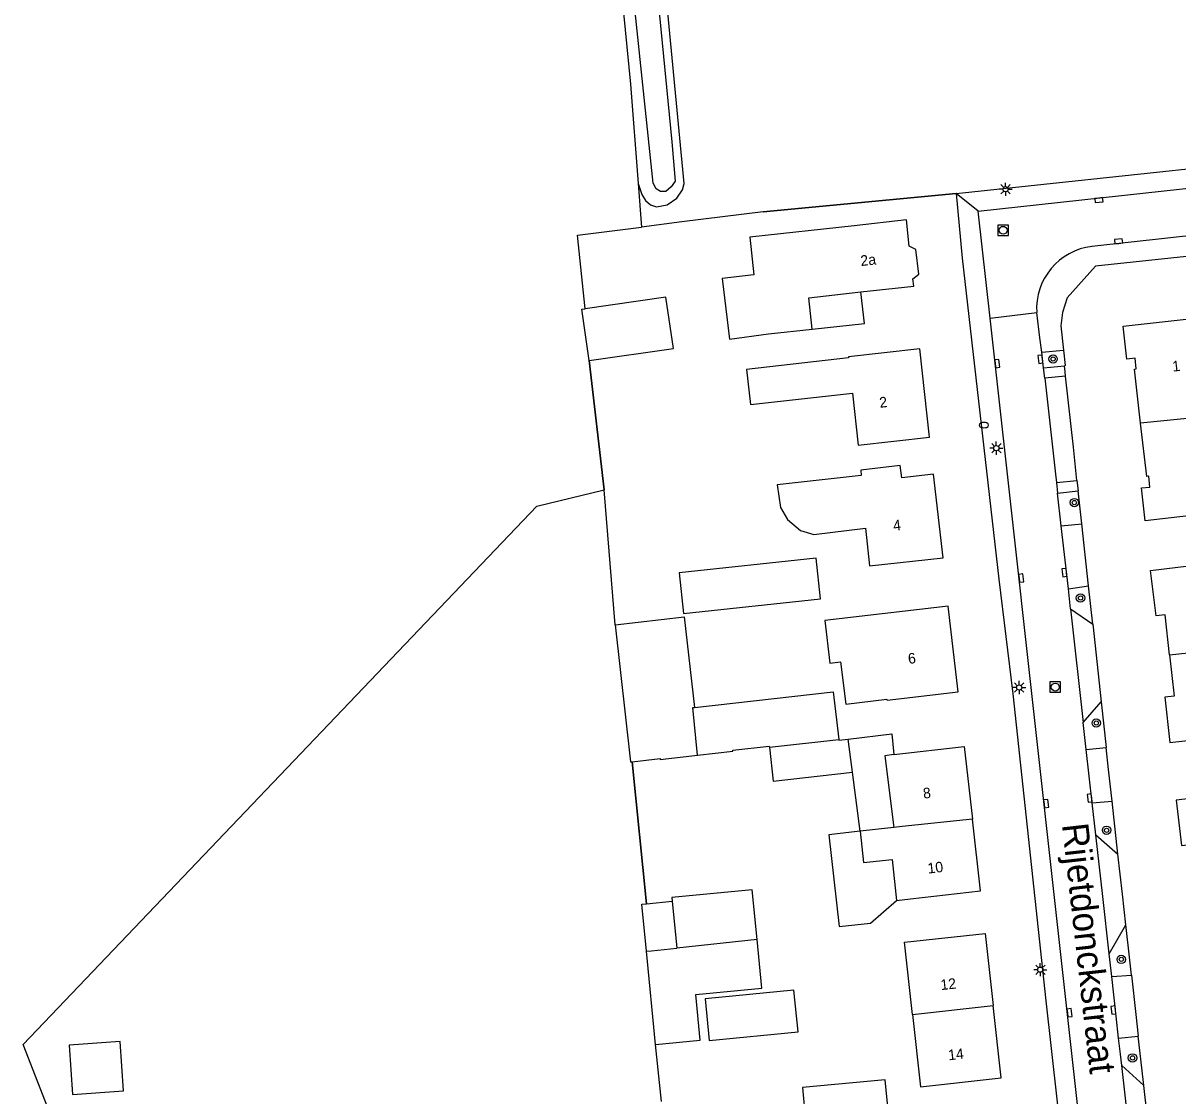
# Model space of a CAD drawing. Extents: x 140000 to 143000, y 403500 to 406000.
# Drawn here: x 140324.8 to 140434.8, y 403882.7 to 403984.8 of the extents above; entities that cross this region are included whole.
import ezdxf

# ---------------------------------------------------------------- set-up
doc = ezdxf.new("R2010")
doc.units = 0
for name, color, linetype in [('gg-afsc-erfafscheiding', 7, 'Continuous'), ('gg-afsc-hekwerk', 7, 'Continuous'), ('gg-anno-huisnummerreeks BGT', 7, 'Continuous'), ('gg-anno-openbare ruimte label', 7, 'Continuous'), ('gg-bbg-bijgebouw', 7, 'Continuous'), ('gg-bbg-gedigitaliseerde bijgebouw', 7, 'Continuous'), ('gg-bbg-hoofdgebouw', 7, 'Continuous'), ('gg-bbg-luifel en loopbrug', 7, 'Continuous'), ('gg-bbg-tussenscheiding', 7, 'Continuous'), ('gg-knt-verharding', 7, 'Continuous'), ('gg-knt-verharding nz', 7, 'Continuous'), ('gg-kntw-bovenkant insteek waterloop', 7, 'Continuous'), ('gg-kntw-waterlijn', 7, 'Continuous'), ('gt-grn-groengrens', 7, 'Continuous'), ('gt-grn-weggrens', 7, 'Continuous'), ('gt-symb-boom', 7, 'Continuous'), ('gt-symb-brandkraan', 7, 'Continuous'), ('gt-symb-kolk', 7, 'Continuous'), ('gt-symb-lichtmast', 7, 'Continuous'), ('gt-symb-rioolschacht', 7, 'Continuous')]:
    doc.layers.add(name, color=color, linetype=linetype)

# ---------------------------------------------------------------- blocks, each defined once
blk = doc.blocks.new('gt0-BOOM')
at = {"layer": 'gt-symb-boom'}
for radius in [0.4, 0.2]:
    blk.add_circle((0, 0), radius, dxfattribs=at)
blk = doc.blocks.new('gt0-KOLK')
at = {"layer": 'gt-symb-kolk'}
blk.add_lwpolyline([(0, 0), (0.38, 0), (0.38, 0.4), (-0.37, 0.4), (-0.37, 0), (0, 0)], dxfattribs=at)
blk = doc.blocks.new('gt0-LMAST')
at = {"layer": 'gt-symb-lichtmast'}
for p, q in [((-0.18, 0.17), (-0.45, 0.44)), ((-0.01, 0.25), (-0.01, 0.62)), ((0.17, 0.17), (0.44, 0.44)), ((-0.26, 0), (-0.63, 0)), ((-0.18, -0.18), (-0.45, -0.45)), ((-0.01, -0.25), (-0.01, -0.63)), ((0.44, -0.45), (0.17, -0.18)), ((0.24, 0), (0.62, 0))]:
    blk.add_line(p, q, dxfattribs=at)
blk.add_circle((-0.01, 0), 0.25, dxfattribs=at)
blk = doc.blocks.new('gt0-RS')
at = {"layer": 'gt-symb-rioolschacht'}
blk.add_lwpolyline([(-0.5, -0.5), (0.5, -0.5), (0.5, 0.5), (-0.5, 0.5)], close=True, dxfattribs=at)
blk.add_circle((0, 0), 0.375, dxfattribs=at)
blk = doc.blocks.new('gt0-BR')
at = {"layer": 'gt-symb-brandkraan'}
for centre, radius, start, end in [((-0.24, 0), 0.206, 107.5669, 252.4331), ((0.6, -2.66), 3, 106.892, 107.5669), ((0, -0.69), 0.938, 73.108, 106.892), ((-0.6, -2.66), 3, 72.4331, 73.108), ((0.24, 0), 0.206, 287.567, 72.4331), ((0.6, 2.66), 3, 252.4331, 253.108), ((0, 0.69), 0.938, 253.108, 286.8921), ((-0.6, 2.66), 3, 286.8921, 287.567)]:
    blk.add_arc(centre, radius, start, end, dxfattribs=at)

msp = doc.modelspace()

# ---------------------------------------------------------------- linework, layer by layer
at = {"layer": 'gg-afsc-erfafscheiding'}
for p, q in [((140423.89, 403953.71), (140424.05, 403952.23)), ((140381.2, 403927.56), (140380.15, 403940.39)), ((140385.61, 403882.17), (140385.05, 403887.6))]:
    msp.add_line(p, q, dxfattribs=at)
for points in [[(140378.37, 403957.63), (140377.61, 403964.65), (140383.71, 403965.42)], [(140439.21, 403962.85), (140439.2, 403962.98), (140426.93, 403961.68), (140424.25, 403958.67), (140423.81, 403957.27), (140423.66, 403956.01), (140423.89, 403953.71)]]:
    msp.add_lwpolyline(points, dxfattribs=at)
at = {"layer": 'gg-afsc-hekwerk'}
for p, q in [((140395.29, 403966.88), (140413.67, 403968.62)), ((140380.15, 403940.39), (140378.73, 403952.71)), ((140384.21, 403901.01), (140382.82, 403914.51)), ((140385.61, 403882.17), (140385.05, 403887.6))]:
    msp.add_line(p, q, dxfattribs=at)
at = {"layer": 'gg-bbg-bijgebouw'}
for p, q in [((140403.81, 403913.52), (140403.4, 403916.68)), ((140385.05, 403887.6), (140384.18, 403896.49))]:
    msp.add_line(p, q, dxfattribs=at)
for points in [[(140378.73, 403952.71), (140386.75, 403953.85), (140386.05, 403958.73), (140378.37, 403957.63)], [(140378.73, 403952.71), (140378.04, 403957.59), (140378.37, 403957.63)], [(140387.71, 403928.64), (140400.75, 403930.03), (140400.34, 403933.9), (140387.29, 403932.51), (140387.71, 403928.64)], [(140381.2, 403927.56), (140387.79, 403928.31), (140388.77, 403919.69)], [(140381.2, 403927.56), (140382.68, 403914.5), (140382.82, 403914.51)], [(140388.77, 403919.69), (140401.97, 403921.19), (140402.51, 403916.64)], [(140402.51, 403916.64), (140402.52, 403916.57), (140403.4, 403916.68)], [(140389.04, 403915.15), (140392.41, 403915.52), (140392.4, 403915.61), (140395.89, 403916.01), (140395.9, 403915.91)], [(140395.9, 403915.91), (140396.27, 403912.66), (140403.81, 403913.52)], [(140382.82, 403914.51), (140385.48, 403914.82), (140385.49, 403914.75), (140389.04, 403915.15)], [(140394.73, 403897.61), (140394.26, 403902.34), (140386.6, 403901.59)], [(140385.05, 403887.6), (140389.3, 403888.01), (140388.88, 403892.36), (140395.18, 403892.98), (140394.73, 403897.61)], [(140407.23, 403881.05), (140406.93, 403884.23), (140399.06, 403883.51), (140399.34, 403880.42)]]:
    msp.add_lwpolyline(points, dxfattribs=at)
at = {"layer": 'gg-bbg-gedigitaliseerde bijgebouw'}
for p in [(140384.21, 403901.01), (140386.6, 403901.59)]:
    msp.add_line(p, (140386.63, 403901.24), dxfattribs=at)
msp.add_lwpolyline([(140384.18, 403896.49), (140383.76, 403900.97), (140384.21, 403901.01)], dxfattribs=at)
at = {"layer": 'gg-bbg-hoofdgebouw'}
msp.add_line((140407.76, 403908.26), (140404.53, 403907.92), dxfattribs=at)
for points in [[(140409.21, 403963.59), (140408.94, 403966.1), (140403.97, 403965.54), (140394.03, 403964.46), (140394.43, 403960.88), (140391.4, 403960.53), (140392.11, 403954.73), (140395.8, 403955.24), (140399.97, 403955.7)], [(140409.56, 403960.49), (140410.12, 403960.93), (140409.85, 403963.28), (140409.21, 403963.59)], [(140431.24, 403946.74), (140430.65, 403951.89), (140430.83, 403951.91), (140430.73, 403952.93), (140429.94, 403952.83), (140429.57, 403955.97), (140439.86, 403957.14), (140439.27, 403962.43), (140442.69, 403962.82)], [(140404.61, 403959.24), (140409.64, 403959.79), (140409.56, 403960.49)], [(140399.97, 403955.7), (140399.64, 403958.69), (140404.61, 403959.24)], [(140393.71, 403951.87), (140394.09, 403948.52), (140403.8, 403949.61), (140404.36, 403944.66), (140411.15, 403945.42), (140410.21, 403953.81), (140403.43, 403953.06), (140403.44, 403952.96), (140393.71, 403951.87)], [(140438.18, 403947.43), (140438.76, 403942.37), (140440.59, 403942.58), (140441.05, 403938.54), (140431.68, 403937.46), (140431.32, 403940.58), (140432.11, 403940.67), (140432.01, 403941.7), (140431.82, 403941.68), (140431.24, 403946.74)], [(140412.44, 403933.94), (140411.53, 403941.89), (140408.49, 403941.54), (140408.35, 403942.71), (140404.59, 403942.29), (140404.64, 403941.76), (140396.65, 403940.88), (140396.95, 403938.72), (140397.63, 403937.58), (140398.85, 403936.52), (140400.12, 403936.16), (140405.04, 403936.74), (140405.43, 403933.16), (140412.44, 403933.94)], [(140434, 403924.69), (140433.57, 403928.52), (140432.71, 403928.42), (140432.17, 403932.72), (140437.13, 403933.34), (140440.13, 403933.68), (140441.06, 403925.48)], [(140407.09, 403920.48), (140407.1, 403920.38), (140413.88, 403921.17), (140412.93, 403929.34), (140401.17, 403927.97), (140401.66, 403923.91), (140402.68, 403924.03), (140403.16, 403920.01), (140407.09, 403920.48)], [(140434, 403924.69), (140434.43, 403920.77), (140433.56, 403920.68), (140434.02, 403916.37), (140441.99, 403917.23), (140441.06, 403925.48)], [(140407.76, 403915.21), (140414.43, 403915.96), (140415.22, 403909.07)], [(140407.76, 403915.21), (140406.88, 403915.09), (140407.76, 403908.26)], [(140443.5, 403903.66), (140442.59, 403911.8), (140434.64, 403910.87), (140435.14, 403906.56), (140436.01, 403906.66), (140436.43, 403902.87)], [(140408, 403901.3), (140409.32, 403901.46), (140416, 403902.22), (140415.22, 403909.07)], [(140404.53, 403907.92), (140404.87, 403904.92), (140407.58, 403905.22), (140408, 403901.3)], [(140409.51, 403890.46), (140408.76, 403897.34), (140416.45, 403898.18), (140417.2, 403891.31)], [(140409.51, 403890.46), (140410.27, 403883.58), (140417.96, 403884.43), (140417.2, 403891.31)]]:
    msp.add_lwpolyline(points, dxfattribs=at)
at = {"layer": 'gg-bbg-luifel en loopbrug'}
msp.add_line((140404.53, 403907.92), (140403.81, 403913.52), dxfattribs=at)
for points in [[(140399.97, 403955.7), (140404.94, 403956.25), (140404.61, 403959.24)], [(140403.4, 403916.68), (140407.54, 403917.17), (140407.76, 403915.21)], [(140404.53, 403907.92), (140401.55, 403907.58), (140402.55, 403898.83), (140405.53, 403899.17), (140408, 403901.3)], [(140389.77, 403891.96), (140390.16, 403887.98), (140398.62, 403888.81), (140398.23, 403892.79), (140389.77, 403891.96)], [(140334.41, 403883.2), (140334.08, 403887.9), (140329.22, 403887.56), (140329.55, 403882.86), (140334.41, 403883.2)]]:
    msp.add_lwpolyline(points, dxfattribs=at)
at = {"layer": 'gg-bbg-tussenscheiding'}
for p, q in [((140438.18, 403947.43), (140431.24, 403946.74)), ((140434, 403924.69), (140441.06, 403925.48)), ((140395.9, 403915.91), (140402.51, 403916.64)), ((140386.63, 403901.24), (140387.07, 403896.77)), ((140384.67, 403896.54), (140387.07, 403896.77)), ((140394.73, 403897.61), (140387.07, 403896.77)), ((140384.18, 403896.49), (140384.67, 403896.54)), ((140409.51, 403890.46), (140417.2, 403891.31))]:
    msp.add_line(p, q, dxfattribs=at)
for points in [[(140389.04, 403915.15), (140388.6, 403919.67), (140388.77, 403919.69)], [(140415.22, 403909.07), (140408.54, 403908.37), (140407.76, 403908.26)]]:
    msp.add_lwpolyline(points, dxfattribs=at)
at = {"layer": 'gg-knt-verharding'}
for p, q in [((140415.78, 403966.93), (140459.74, 403971.72)), ((140415.78, 403966.93), (140413.67, 403968.62)), ((140460.21, 403967.23), (140426.61, 403963.58)), ((140416.91, 403956.75), (140415.78, 403966.93)), ((140421.82, 403953.5), (140423.89, 403953.71)), ((140422, 403952.01), (140421.82, 403953.5)), ((140378.73, 403952.71), (140380.15, 403940.39)), ((140422, 403952.01), (140424, 403952.22)), ((140422.11, 403951.02), (140422, 403952.01)), ((140424.05, 403952.23), (140424, 403952.22)), ((140424.1, 403951.22), (140422.11, 403951.02)), ((140423.22, 403941.09), (140425.18, 403941.3)), ((140423.22, 403941.09), (140423.34, 403940.1)), ((140425.18, 403941.3), (140425.29, 403940.31)), ((140423.34, 403940.1), (140425.29, 403940.31)), ((140423.69, 403936.97), (140423.34, 403940.1)), ((140425.63, 403937.18), (140425.29, 403940.31)), ((140423.69, 403936.97), (140425.63, 403937.18)), ((140426.28, 403931.27), (140425.63, 403937.18)), ((140424.36, 403930.99), (140426.28, 403931.27)), ((140424.57, 403929.08), (140424.36, 403930.99)), ((140426.68, 403927.62), (140426.28, 403931.27)), ((140424.57, 403929.08), (140425.78, 403918.27)), ((140424.57, 403929.08), (140426.68, 403927.62)), ((140426.68, 403927.62), (140427.48, 403920.24)), ((140425.78, 403918.27), (140427.48, 403920.24)), ((140427.48, 403920.24), (140427.96, 403915.87)), ((140426.07, 403915.68), (140425.78, 403918.27)), ((140426.07, 403915.68), (140427.96, 403915.87)), ((140382.82, 403914.51), (140384.21, 403901.01)), ((140426.64, 403910.61), (140428.52, 403910.78)), ((140426.99, 403907.55), (140426.64, 403910.61)), ((140429.08, 403905.72), (140428.52, 403910.78)), ((140426.99, 403907.55), (140429.08, 403905.72)), ((140428.25, 403896.24), (140429.83, 403898.99)), ((140428.5, 403894.08), (140428.25, 403896.24)), ((140428.5, 403894.08), (140430.37, 403894.22)), ((140429.15, 403888.21), (140431.01, 403888.4)), ((140429.45, 403885.6), (140431.54, 403883.7))]:
    msp.add_line(p, q, dxfattribs=at)
for points in [[(140413.67, 403968.62), (140447.08, 403972.15), (140457.58, 403973.3)], [(140413.67, 403968.62), (140395.29, 403966.88), (140387.55, 403965.9), (140383.71, 403965.42)], [(140413.67, 403968.62), (140414.25, 403962.45), (140417.74, 403931.9), (140419.08, 403921), (140422.22, 403891.78), (140425.88, 403859.14), (140426.34, 403855.42)], [(140421.82, 403953.5), (140421.64, 403954.88), (140421.35, 403957.27)], [(140428.85, 403849.38), (140428.83, 403849.61), (140416.91, 403956.75)], [(140424.1, 403951.22), (140424.06, 403951.64), (140424, 403952.22)], [(140422.11, 403951.02), (140423.13, 403941.89), (140423.22, 403941.09)], [(140425.18, 403941.3), (140424.84, 403944.47), (140424.1, 403951.22)], [(140428.52, 403910.78), (140428.18, 403913.8), (140427.96, 403915.87)], [(140429.83, 403898.99), (140429.51, 403901.93), (140429.08, 403905.72)], [(140430.37, 403894.22), (140430.08, 403896.79), (140429.83, 403898.99)], [(140430.37, 403894.22), (140430.78, 403890.48), (140431.01, 403888.4)], [(140429.45, 403885.6), (140429.32, 403886.7), (140429.15, 403888.21)], [(140431.54, 403883.7), (140431.35, 403885.38), (140431.01, 403888.4)], [(140432.29, 403876.86), (140432.17, 403878.06), (140431.54, 403883.7)]]:
    msp.add_lwpolyline(points, dxfattribs=at)
msp.add_arc((140427.31, 403957.65), 5.97, 96.7037, 183.6137, dxfattribs=at)
at = {"layer": 'gg-knt-verharding nz'}
for p, q in [((140424.36, 403930.99), (140423.69, 403936.97)), ((140426.64, 403910.61), (140426.07, 403915.68)), ((140430.73, 403874.18), (140429.45, 403885.6))]:
    msp.add_line(p, q, dxfattribs=at)
for points in [[(140428.25, 403896.24), (140427.64, 403901.71), (140426.99, 403907.55)], [(140429.15, 403888.21), (140428.92, 403890.31), (140428.5, 403894.08)]]:
    msp.add_lwpolyline(points, dxfattribs=at)
at = {"layer": 'gg-kntw-bovenkant insteek waterloop'}
for points in [[(140383.39, 403969.57), (140383.74, 403968.5), (140384.11, 403967.95), (140384.58, 403967.52), (140385.15, 403967.33), (140386.16, 403967.54), (140387.08, 403968.16), (140387.62, 403968.95), (140387.77, 403969.55), (140383.25, 404017.1)], [(140379.51, 404011.38), (140382.68, 403979.03), (140383.39, 403969.57)]]:
    msp.add_lwpolyline(points, dxfattribs=at)
at = {"layer": 'gg-kntw-waterlijn'}
msp.add_lwpolyline([(140371.91, 404097.95), (140366.93, 404150.41), (140365.99, 404159.4), (140366.02, 404160.46), (140366.42, 404160.96), (140366.86, 404161.43), (140367.35, 404161.52), (140367.96, 404161.08), (140368.54, 404160.54), (140369.12, 404153.84), (140378.48, 404058.08), (140381.51, 404028.61), (140384.12, 403998.92), (140386.61, 403973.54), (140386.92, 403969.8), (140386.55, 403969.26), (140386.04, 403968.79), (140385.52, 403968.81), (140385.12, 403969.04), (140384.83, 403969.59), (140379.69, 404018.54), (140375.97, 404056.84), (140371.91, 404097.95)], dxfattribs=at)
at = {"layer": 'gt-grn-groengrens'}
msp.add_line((140383.39, 403969.57), (140383.71, 403965.42), dxfattribs=at)
msp.add_lwpolyline([(140387.39, 403779.73), (140370.14, 403777.98), (140366.61, 403780.36), (140324.84, 403887.61), (140373.74, 403938.86), (140380.15, 403940.39)], dxfattribs=at)
at = {"layer": 'gt-grn-weggrens'}
msp.add_line((140416.91, 403956.75), (140421.35, 403957.27), dxfattribs=at)

# ---------------------------------------------------------------- block references
at = {"layer": 'gt-symb-boom'}
for p in [(140422.91, 403952.86), (140424.93, 403939.19), (140425.52, 403930.11), (140427.02, 403918.21), (140428, 403908), (140429.4, 403895.71), (140430.47, 403886.33)]:
    msp.add_blockref('gt0-BOOM', p, dxfattribs=at)
at = {"layer": 'gt-symb-brandkraan'}
msp.add_blockref('gt0-BR', (140416.32, 403946.56), dxfattribs=at)
at = {"layer": 'gt-symb-kolk'}
for p, rotation in [((140427.25, 403968.18), -173.78190170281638), ((140429.16, 403963.86), 6.2020525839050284), ((140421.89, 403952.86), 97.04693902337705), ((140417.4, 403952.4), -83.65178725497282), ((140419.67, 403931.99), -83.6517872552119), ((140424.18, 403932.55), 96.39633348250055), ((140426.59, 403911.08), 96.40435272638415), ((140422.05, 403910.52), -83.6517872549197), ((140428.85, 403890.9), 96.38831398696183), ((140424.27, 403890.61), -83.65178725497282)]:
    msp.add_blockref('gt0-KOLK', p, dxfattribs=dict(at, rotation=rotation))
at = {"layer": 'gt-symb-lichtmast'}
for p in [(140418.39, 403969.02), (140417.51, 403944.37), (140419.68, 403921.59), (140421.7, 403894.73)]:
    msp.add_blockref('gt0-LMAST', p, dxfattribs=at)
at = {"layer": 'gt-symb-rioolschacht'}
for p in [(140418.15, 403965.11), (140423.11, 403921.63)]:
    msp.add_blockref('gt0-RS', p, dxfattribs=at)

# ---------------------------------------------------------------- texts
at = {"layer": 'gg-anno-huisnummerreeks BGT'}
for s, rotation, p in [('2a', 6.3, (140404.62, 403961.7)), ('1', 6.5, (140434.31, 403951.65)), ('2', 6.3, (140406.42, 403948.21)), ('4', 6.5, (140407.73, 403936.5)), ('6', 6.6, (140409.15, 403923.83)), ('8', 6.5, (140410.58, 403911.01)), ('10', 6.5, (140411.01, 403903.87)), ('12', 6.2, (140412.24, 403892.78)), ('14', 6.2, (140412.97, 403886.1))]:
    msp.add_text(s, height=1, rotation=rotation, dxfattribs=at).set_placement(p)
at = {"layer": 'gg-anno-openbare ruimte label'}
msp.add_text('Rijetdonckstraat', height=2.5, rotation=276.4, dxfattribs=at).set_placement((140423.75, 403908.55))

doc.saveas('drawing.dxf')
